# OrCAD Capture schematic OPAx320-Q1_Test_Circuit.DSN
size A; title: OPAx320-Q1 Precision, 20-MHz, 0.9-pA, Low-Noise, RRIO,; rev: 1.6; note: Datasheet: SLOS884B  EVM: N/A
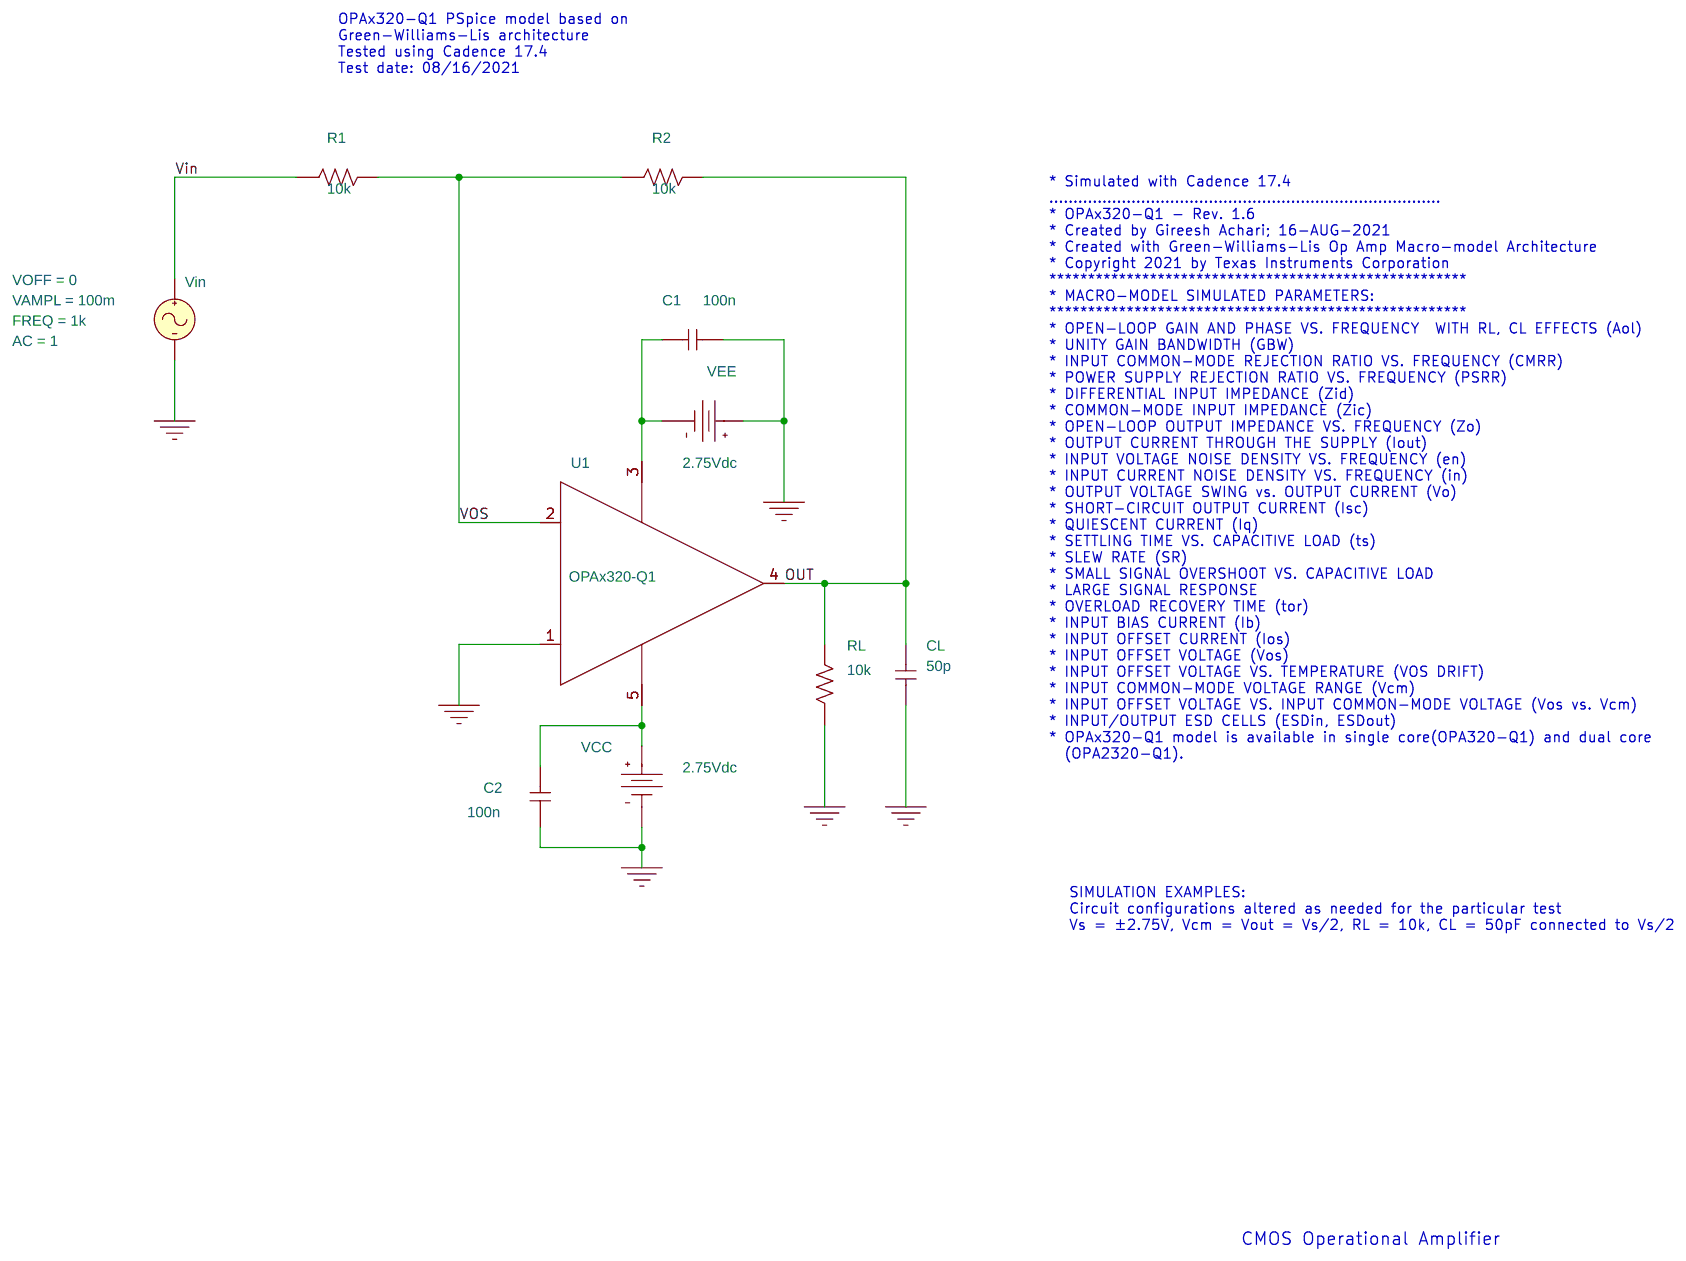
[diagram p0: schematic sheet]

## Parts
C1  100n  [cap196]
C2  100n  [cap196]
CL  50p  [RAD/CK05]
R1  10k  [AXRC05]
R2  10k  [AXRC05]
RL  10k  [AXRC05]
U1  OPAx320-Q1
VCC  VDC
VEE  VDC
Vin  VSIN

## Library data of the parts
C1 C2 CL = C
R1 R2 RL = R
U1 = OPAx320-Q1
VCC VEE = VDC: DC: 2.75Vdc
Vin = VSIN: AC: 1; FREQ: 1k; VAMPL: 100m; VOFF: 0

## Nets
Vin: R1.1 Vin.1(+)
0: C1.2 C2.1 CL.1 RL.1 U1.1(IN+) VCC.1(-) VEE.0(+) Vin.2(-)
OUT: CL.2 R2.2 RL.2 U1.4(OUT)
VOS: R1.2 R2.1 U1.2(IN-)
N27303: C1.1 U1.3(VEE) VEE.1(-)
N27354: C2.2 U1.5(VCC) VCC.0(+)

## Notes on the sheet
- OPAx320-Q1 PSpice model based on
  Green-Williams-Lis architecture
  Tested using Cadence 17.4
  Test date: 08/16/2021
- * Simulated with Cadence 17.4
  .................................................................................
  * OPAx320-Q1 - Rev. 1.6
  * Created by Gireesh Achari; 16-AUG-2021
  * Created with Green-Williams-Lis Op Amp Macro-model Architecture
  * Copyright 2021 by Texas Instruments Corporation
  ******************************************************
  * MACRO-MODEL SIMULATED PARAMETERS:
  ******************************************************
  * OPEN-LOOP GAIN AND PHASE VS. FREQUENCY  WITH RL, CL EFFECTS (Aol)
  * UNITY GAIN BANDWIDTH (GBW)
  * INPUT COMMON-MODE REJECTION RATIO VS. FREQUENCY (CMRR)
  * POWER SUPPLY REJECTION RATIO VS. FREQUENCY (PSRR)
  * DIFFERENTIAL INPUT IMPEDANCE (Zid)
  * COMMON-MODE INPUT IMPEDANCE (Zic)
  * OPEN-LOOP OUTPUT IMPEDANCE VS. FREQUENCY (Zo)
  * OUTPUT CURRENT THROUGH THE SUPPLY (Iout)
  * INPUT VOLTAGE NOISE DENSITY VS. FREQUENCY (en)
  * INPUT CURRENT NOISE DENSITY VS. FREQUENCY (in)
  * OUTPUT VOLTAGE SWING vs. OUTPUT CURRENT (Vo)
  * SHORT-CIRCUIT OUTPUT CURRENT (Isc)
  * QUIESCENT CURRENT (Iq)
  * SETTLING TIME VS. CAPACITIVE LOAD (ts)
  * SLEW RATE (SR)
  * SMALL SIGNAL OVERSHOOT VS. CAPACITIVE LOAD
  * LARGE SIGNAL RESPONSE
  * OVERLOAD RECOVERY TIME (tor)
  * INPUT BIAS CURRENT (Ib)
  * INPUT OFFSET CURRENT (Ios)
  * INPUT OFFSET VOLTAGE (Vos)
  * INPUT OFFSET VOLTAGE VS. TEMPERATURE (VOS DRIFT)
  * INPUT COMMON-MODE VOLTAGE RANGE (Vcm)
  * INPUT OFFSET VOLTAGE VS. INPUT COMMON-MODE VOLTAGE (Vos vs. Vcm)
  * INPUT/OUTPUT ESD CELLS (ESDin, ESDout)
  * OPAx320-Q1 model is available in single core(OPA320-Q1) and dual core
    (OPA2320-Q1).
- SIMULATION EXAMPLES:
  Circuit configurations altered as needed for the particular test
  Vs = ±2.75V, Vcm = Vout = Vs/2, RL = 10k, CL = 50pF connected to Vs/2
- CMOS Operational Amplifier
